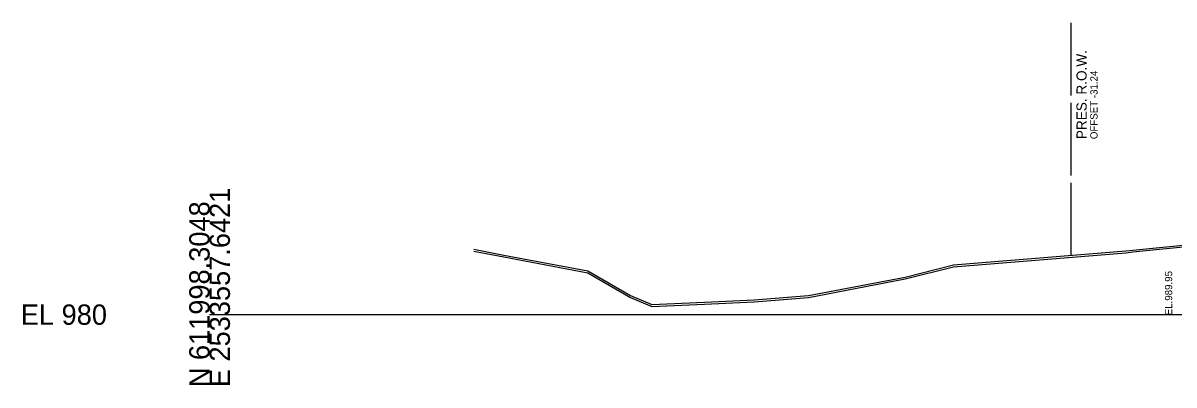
# Model space of a CAD drawing. Extents: x -26 to 303, y -23 to 1542.
# Drawn here: x -25.7 to 132.8, y 990.3 to 1040.2 of the extents above; entities that cross this region are included whole.
import ezdxf

# ---------------------------------------------------------------- set-up
doc = ezdxf.new("R2010")
doc.units = 0
for name, color, linetype in [('DESIGN - SHEET - Light Grid', 7, 'Continuous'), ('DESIGN - TYPICAL - Subgrade Tie Text', 7, 'Continuous'), ('SURVEY - GROUND - Bottom of Topsoil Layer', 7, 'Continuous'), ('SURVEY - GROUND - Top of Ground', 7, 'Continuous'), ('SURVEY - PROPERTY - ROW Lines', 7, 'Continuous'), ('SURVEY - PROPERTY - ROW Lines Text', 7, 'Continuous')]:
    doc.layers.add(name, color=color, linetype=linetype)

msp = doc.modelspace()

# ---------------------------------------------------------------- linework, layer by layer
at = {"layer": 'DESIGN - SHEET - Light Grid'}
msp.add_line((0, 1000), (149.88, 1000), dxfattribs=at)
at = {"layer": 'SURVEY - GROUND - Bottom of Topsoil Layer'}
for p, q in [((36.41, 1008.76), (40.53, 1007.96)), ((102.44, 1006.59), (126.16, 1008.53)), ((126.16, 1008.53), (127.12, 1008.63)), ((127.12, 1008.63), (135.91, 1009.5)), ((40.53, 1007.96), (52.08, 1005.76)), ((95.8, 1004.93), (102.44, 1006.59)), ((52.08, 1005.76), (57.98, 1002.37)), ((82.46, 1002.37), (95.8, 1004.93)), ((57.98, 1002.37), (60.92, 1001.14)), ((68.14, 1001.46), (74.97, 1001.78)), ((74.97, 1001.78), (82.46, 1002.37)), ((60.92, 1001.14), (68.14, 1001.46))]:
    msp.add_line(p, q, dxfattribs=at)
at = {"layer": 'SURVEY - GROUND - Top of Ground'}
msp.add_lwpolyline([(36.41, 1009.01), (40.53, 1008.21), (52.08, 1006.01), (57.98, 1002.62), (60.92, 1001.39), (68.14, 1001.71), (74.97, 1002.03), (82.46, 1002.62), (95.8, 1005.18), (102.44, 1006.84), (126.16, 1008.78), (127.12, 1008.88), (135.91, 1009.75)], dxfattribs=at)
at = {"layer": 'SURVEY - PROPERTY - ROW Lines'}
for p, q in [((118.63, 1030.17), (118.63, 1040.17)), ((118.63, 1019.17), (118.63, 1029.17)), ((118.63, 1008.17), (118.63, 1018.17))]:
    msp.add_line(p, q, dxfattribs=at)

# ---------------------------------------------------------------- texts
at = {"layer": 'DESIGN - SHEET - Light Grid'}
for s, p in [('E 2533557.6421', (2.8, 990)), ('N 611998.3048', (0, 990))]:
    msp.add_text(s, height=2.8, rotation=90, dxfattribs=at).set_placement(p)
msp.add_text('EL 980', height=2.8, dxfattribs=at).set_placement((-26, 998.6))
at = {"layer": 'DESIGN - TYPICAL - Subgrade Tie Text'}
msp.add_text('EL.989.95', height=1, rotation=90, dxfattribs=at).set_placement((132.56, 999.91))
at = {"layer": 'SURVEY - PROPERTY - ROW Lines Text'}
for s, height, p in [('PRES. R.O.W.', 1.4, (120.78, 1024.17)), ('OFFSET -31.24', 1, (122.28, 1024.17))]:
    msp.add_text(s, height=height, rotation=90, dxfattribs=at).set_placement(p)

doc.saveas('drawing.dxf')
